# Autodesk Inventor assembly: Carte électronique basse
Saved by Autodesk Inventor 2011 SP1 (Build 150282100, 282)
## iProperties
Created: 2010-12
Part Number: Carte électronique basse
Document SubType Name: Assembly
Designer: eric
Author: eric
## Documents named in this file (2)
- D:\eduinventor\maquettesaip2011\machineàpain\Workspace\Carte électronique basse.iam
- D:\eduinventor\maquettesaip2011\machineàpain\Workspace\carte electronique basse.ipt
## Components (1 placed, 1 different names)
1. carte electronique basse:1
